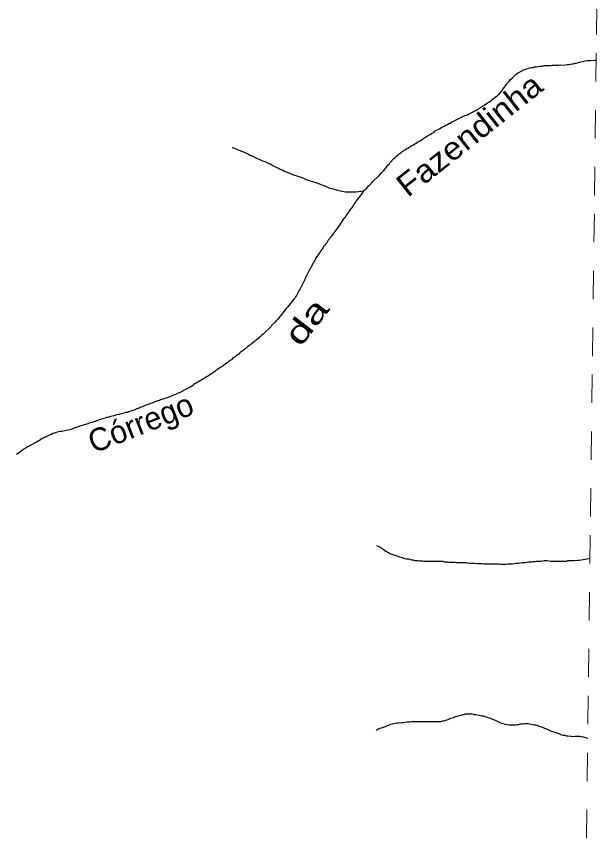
# Model space of a CAD drawing. Extents: x 652.3 to 678, y 7316.9 to 7344.9.
# Drawn here: x 675.832 to 677.88, y 7329.942 to 7332.83 of the extents above; entities that cross this region are included whole.
import ezdxf
from ezdxf.enums import TextEntityAlignment as Align

# ---------------------------------------------------------------- set-up
doc = ezdxf.new("R2010")
doc.units = 0
doc.header["$LTSCALE"] = 0.032
doc.linetypes.add('SHORT_DASHED', pattern=[2.7, 1.5, -1.2])
doc.layers.add('53', color=7, linetype='SHORT_DASHED', lineweight=13)
doc.layers.add('7', color=7, linetype='Continuous', lineweight=25)
doc.layers.add('61', color=7, linetype='Continuous')

msp = doc.modelspace()

# ---------------------------------------------------------------- linework, layer by layer
at = {"layer": '53'}
msp.add_lwpolyline([(677.795, 7326.5503), (677.802, 7327.1153), (677.8091, 7327.6804), (677.8162, 7328.2454), (677.8232, 7328.8105), (677.8303, 7329.3756), (677.8374, 7329.9406), (677.8444, 7330.5057), (677.8515, 7331.0708), (677.8585, 7331.6358), (677.8656, 7332.2009), (677.8726, 7332.766), (677.8797, 7333.331)], dxfattribs=at)
at = {"layer": '7'}
for points in [[(677.2561, 7332.3955), (677.2609, 7332.3979), (677.2648, 7332.4011), (677.2688, 7332.4043), (677.2736, 7332.4067), (677.2776, 7332.4098), (677.2823, 7332.4122), (677.2871, 7332.4154), (677.2919, 7332.4186), (677.2967, 7332.421), (677.3014, 7332.4234), (677.3054, 7332.4274), (677.3102, 7332.4297), (677.315, 7332.4329), (677.3197, 7332.4353), (677.3245, 7332.4385), (677.3388, 7332.4457), (677.3436, 7332.4488), (677.3484, 7332.4504), (677.3532, 7332.4536), (677.3579, 7332.4552), (677.3619, 7332.4584), (677.3667, 7332.46), (677.3858, 7332.4695), (677.3905, 7332.4719), (677.4096, 7332.4815), (677.4192, 7332.4846), (677.424, 7332.487), (677.4287, 7332.4902), (677.4335, 7332.4918), (677.4383, 7332.495), (677.4431, 7332.4974), (677.4478, 7332.4998), (677.4526, 7332.5029), (677.4622, 7332.5077), (677.4661, 7332.5109), (677.4709, 7332.5141), (677.4757, 7332.5165), (677.4797, 7332.5197), (677.4844, 7332.5228), (677.4892, 7332.526), (677.494, 7332.5284), (677.498, 7332.5316), (677.5019, 7332.5348), (677.5059, 7332.538), (677.5099, 7332.5411), (677.5139, 7332.5443), (677.5179, 7332.5475), (677.5226, 7332.5507), (677.5266, 7332.5539), (677.5306, 7332.5571), (677.5338, 7332.5618), (677.5401, 7332.5698), (677.5433, 7332.5746), (677.5497, 7332.5825), (677.5561, 7332.5921), (677.564, 7332.6), (677.5704, 7332.608), (677.5744, 7332.612), (677.5783, 7332.6159), (677.5863, 7332.6239), (677.5903, 7332.6271), (677.595, 7332.6303), (677.599, 7332.6334), (677.6181, 7332.643), (677.6277, 7332.6462), (677.6332, 7332.6478), (677.638, 7332.6494), (677.6436, 7332.6501), (677.6491, 7332.6509), (677.6547, 7332.6525), (677.6619, 7332.6533), (677.6674, 7332.6541), (677.673, 7332.6549), (677.6786, 7332.6557), (677.6842, 7332.6557), (677.6889, 7332.6573), (677.7056, 7332.6573), (677.7112, 7332.6581), (677.7168, 7332.6589), (677.7391, 7332.6589), (677.747, 7332.6597), (677.7582, 7332.6589), (677.7693, 7332.6605), (677.7749, 7332.6605), (677.7804, 7332.6621), (677.786, 7332.6629), (677.7916, 7332.6637), (677.7964, 7332.6653), (677.8019, 7332.6661), (677.8075, 7332.6677), (677.8123, 7332.6692), (677.8178, 7332.67), (677.8226, 7332.6716), (677.8274, 7332.6732), (677.833, 7332.674), (677.8385, 7332.6756), (677.8497, 7332.6756), (677.8672, 7332.6764), (677.8715, 7332.6766)], [(676.5905, 7332.3694), (676.5909, 7332.3693), (676.5957, 7332.3677), (676.6004, 7332.3661), (676.6052, 7332.3645), (676.6148, 7332.3597), (676.6195, 7332.3581), (676.6243, 7332.3557), (676.6338, 7332.3526), (676.6482, 7332.3454), (676.6529, 7332.3422), (676.6577, 7332.3406), (676.6625, 7332.3382), (676.6673, 7332.3359), (676.672, 7332.3335), (676.6768, 7332.3319), (676.6816, 7332.3295), (676.6864, 7332.3279), (676.6911, 7332.3255), (676.6959, 7332.3239), (676.7007, 7332.3215), (676.7055, 7332.3199), (676.7198, 7332.3128), (676.7246, 7332.3112), (676.7341, 7332.3064), (676.7389, 7332.304), (676.7628, 7332.2921), (676.7675, 7332.2905), (676.7723, 7332.2873), (676.7771, 7332.2849), (676.7818, 7332.2833), (676.7866, 7332.2809), (676.7962, 7332.2778), (676.8009, 7332.2754), (676.8105, 7332.2722), (676.8153, 7332.2706), (676.8248, 7332.2674), (676.8304, 7332.2658), (676.8352, 7332.2642), (676.8399, 7332.2619), (676.8447, 7332.2603), (676.8543, 7332.2555), (676.8686, 7332.2507), (676.8741, 7332.2491), (676.8885, 7332.2443), (676.8932, 7332.2428), (676.898, 7332.2412), (676.9028, 7332.2388), (676.9171, 7332.234), (676.9219, 7332.2316), (676.9267, 7332.23), (676.9314, 7332.2276), (676.9362, 7332.226), (676.941, 7332.2245), (676.9466, 7332.2237), (676.9609, 7332.2189), (676.9664, 7332.2181), (676.9712, 7332.2165), (676.9776, 7332.2157), (676.984, 7332.2149), (676.9887, 7332.2133), (677.0166, 7332.2133), (677.0261, 7332.2133), (677.0532, 7332.2165)], [(677.0532, 7332.2165), (677.0643, 7332.226), (677.0675, 7332.23), (677.0707, 7332.234), (677.0747, 7332.238), (677.0786, 7332.2412), (677.0818, 7332.2451), (677.0858, 7332.2491), (677.0898, 7332.2531), (677.1017, 7332.265), (677.1057, 7332.2682), (677.1089, 7332.2722), (677.1168, 7332.2802), (677.12, 7332.2841), (677.124, 7332.2881), (677.1335, 7332.3), (677.1367, 7332.304), (677.1399, 7332.308), (677.1439, 7332.312), (677.1471, 7332.3168), (677.159, 7332.3287), (677.163, 7332.3319), (677.1662, 7332.3359), (677.1701, 7332.3398), (677.1749, 7332.343), (677.1789, 7332.347), (677.1837, 7332.3502), (677.1876, 7332.3534), (677.1924, 7332.3565), (677.1964, 7332.3597), (677.2012, 7332.3621), (677.2059, 7332.3653), (677.2107, 7332.3685), (677.2155, 7332.3709), (677.2195, 7332.374), (677.2243, 7332.3764), (677.229, 7332.3788), (677.2338, 7332.382), (677.2386, 7332.3844), (677.2426, 7332.3876), (677.2521, 7332.3923), (677.2561, 7332.3955)], [(677.0532, 7332.2165), (677.0452, 7332.2038), (677.042, 7332.1998), (677.0357, 7332.1926), (677.0277, 7332.1815), (677.0245, 7332.1767), (677.0214, 7332.1727), (677.0182, 7332.168), (677.0158, 7332.1632), (677.0126, 7332.1592), (677.0094, 7332.1544), (677.0062, 7332.1505), (677.003, 7332.1457), (676.9999, 7332.1417), (676.9967, 7332.1369), (676.9935, 7332.1322), (676.9903, 7332.1282), (676.9871, 7332.1234), (676.984, 7332.1194), (676.9808, 7332.1146), (676.9776, 7332.1107), (676.968, 7332.0963), (676.9649, 7332.0916), (676.9617, 7332.0868), (676.9553, 7332.0788), (676.9489, 7332.0693), (676.9426, 7332.0613), (676.9394, 7332.0566), (676.9354, 7332.0526), (676.933, 7332.0478), (676.9291, 7332.0438), (676.9267, 7332.0391), (676.9235, 7332.0343)], [(676.9235, 7332.0343), (676.9203, 7332.0303), (676.9171, 7332.0255), (676.9139, 7332.0216), (676.9076, 7332.012), (676.9012, 7332.004), (676.8988, 7331.9993), (676.8956, 7331.9953), (676.8924, 7331.9905), (676.8893, 7331.9857), (676.8829, 7331.9762), (676.8813, 7331.9714), (676.8781, 7331.9674), (676.8757, 7331.9627), (676.8726, 7331.9579), (676.871, 7331.9531), (676.8678, 7331.9483), (676.8654, 7331.9436), (676.863, 7331.9388), (676.8558, 7331.9245), (676.8535, 7331.9197), (676.8503, 7331.9149), (676.8487, 7331.9102), (676.8463, 7331.9054), (676.8447, 7331.9006), (676.8375, 7331.8863), (676.8352, 7331.8815), (676.8304, 7331.872), (676.8272, 7331.8672), (676.8248, 7331.8624), (676.82, 7331.8529), (676.8169, 7331.8489), (676.8137, 7331.8441), (676.8113, 7331.8393), (676.8081, 7331.8354), (676.7858, 7331.8075), (676.7826, 7331.8035), (676.7604, 7331.7757), (676.7564, 7331.7717), (676.75, 7331.7638), (676.746, 7331.7598), (676.7429, 7331.7558), (676.7309, 7331.7439), (676.7277, 7331.7399), (676.7039, 7331.716), (676.6999, 7331.7128), (676.6959, 7331.7096), (676.6919, 7331.7057), (676.688, 7331.7025), (676.684, 7331.6985), (676.68, 7331.6953), (676.676, 7331.6921), (676.672, 7331.689), (676.6681, 7331.6858), (676.6641, 7331.6826), (676.6593, 7331.6794), (676.6553, 7331.6754), (676.6506, 7331.6722), (676.6466, 7331.6691), (676.6426, 7331.6659), (676.6386, 7331.6627), (676.6346, 7331.6595), (676.6307, 7331.6563), (676.6267, 7331.6531), (676.6219, 7331.65), (676.6179, 7331.6468), (676.614, 7331.6428), (676.61, 7331.6396), (676.6052, 7331.6364), (676.6012, 7331.6333), (676.5972, 7331.6301), (676.5925, 7331.6269), (676.5885, 7331.6229), (676.5837, 7331.6197), (676.5797, 7331.6165), (676.5758, 7331.6134), (676.571, 7331.6102), (676.5662, 7331.607), (676.5622, 7331.6038), (676.5583, 7331.6006), (676.5535, 7331.5982), (676.5495, 7331.5951), (676.5447, 7331.5919), (676.54, 7331.5887), (676.5352, 7331.5855), (676.5312, 7331.5823), (676.5264, 7331.5792), (676.5217, 7331.576), (676.5169, 7331.5728), (676.5121, 7331.5696), (676.5073, 7331.5664), (676.5026, 7331.5632), (676.4978, 7331.5608), (676.4938, 7331.5577), (676.489, 7331.5553), (676.4843, 7331.5521), (676.4795, 7331.5497), (676.4755, 7331.5465), (676.466, 7331.5418), (676.4612, 7331.5386), (676.4564, 7331.5354)], [(676.4564, 7331.5354), (676.4524, 7331.5322), (676.4485, 7331.529), (676.4294, 7331.5195), (676.4246, 7331.5163), (676.4055, 7331.5067), (676.4007, 7331.5052), (676.3912, 7331.5004), (676.3816, 7331.4972), (676.3721, 7331.4924), (676.3625, 7331.4892), (676.3577, 7331.4876), (676.3434, 7331.4829), (676.3386, 7331.4813), (676.3339, 7331.4797), (676.3283, 7331.4781), (676.3235, 7331.4757), (676.3188, 7331.4741), (676.314, 7331.4725), (676.3092, 7331.4701), (676.3044, 7331.4685), (676.2997, 7331.4662), (676.2853, 7331.4614), (676.2806, 7331.459), (676.2758, 7331.4574), (676.2702, 7331.4558), (676.2654, 7331.4534), (676.2607, 7331.451), (676.2559, 7331.4495), (676.2511, 7331.4479), (676.2463, 7331.4455), (676.2408, 7331.4447), (676.236, 7331.4423), (676.2312, 7331.4407), (676.2217, 7331.4375), (676.2161, 7331.4367), (676.2105, 7331.4351), (676.201, 7331.4319), (676.1954, 7331.4304), (676.1899, 7331.4296), (676.1843, 7331.4288), (676.1747, 7331.4256), (676.1692, 7331.4248), (676.1644, 7331.4232), (676.1596, 7331.4216), (676.1548, 7331.42), (676.1493, 7331.4192), (676.1445, 7331.4176), (676.1397, 7331.416), (676.1342, 7331.4144), (676.1294, 7331.4129), (676.1238, 7331.4113), (676.119, 7331.4089), (676.1047, 7331.4041), (676.0991, 7331.4025), (676.088, 7331.3993), (676.0832, 7331.3977), (676.0785, 7331.3961), (676.0641, 7331.3914), (676.0586, 7331.3898), (676.049, 7331.3866), (676.0442, 7331.385), (676.0395, 7331.3834), (676.0339, 7331.3818), (676.0291, 7331.3802), (676.0244, 7331.3778), (676.0196, 7331.3762), (676.014, 7331.3755), (676.0076, 7331.3739), (676.0029, 7331.3723), (675.9917, 7331.3707), (675.9862, 7331.3699), (675.9806, 7331.3691), (675.9758, 7331.3675), (675.9702, 7331.3659), (675.9655, 7331.3643), (675.9607, 7331.3627), (675.9559, 7331.3603), (675.9511, 7331.3587), (675.9368, 7331.3516), (675.9321, 7331.35), (675.9273, 7331.3468), (675.9225, 7331.3452), (675.9177, 7331.342), (675.913, 7331.3389), (675.9082, 7331.3365), (675.9034, 7331.3333), (675.8986, 7331.3309), (675.8947, 7331.3277), (675.8899, 7331.3261), (675.8851, 7331.3229), (675.8803, 7331.3206), (675.8756, 7331.3174), (675.8708, 7331.3158), (675.866, 7331.3134), (675.862, 7331.3102), (675.8573, 7331.3078), (675.8533, 7331.3046), (675.8405, 7331.2951), (675.8329, 7331.2894), (675.8323, 7331.2889)], [(677.0986, 7330.969), (677.099, 7330.9688), (677.1049, 7330.9665), (677.1089, 7330.9649), (677.1136, 7330.9625), (677.1176, 7330.9593), (677.1224, 7330.9561), (677.1264, 7330.9529), (677.1312, 7330.9498), (677.1359, 7330.9474), (677.1407, 7330.9442), (677.1455, 7330.9418), (677.1598, 7330.937), (677.1646, 7330.9354), (677.1741, 7330.9323), (677.1789, 7330.9299), (677.1845, 7330.9283), (677.1892, 7330.9267), (677.194, 7330.9251), (677.1988, 7330.9235), (677.2044, 7330.9227), (677.2107, 7330.9219), (677.2163, 7330.9211), (677.2219, 7330.9195), (677.2274, 7330.9187), (677.2322, 7330.9171), (677.2378, 7330.9171), (677.2433, 7330.9163), (677.2489, 7330.9155), (677.2601, 7330.9155), (677.2656, 7330.9148), (677.2712, 7330.914), (677.3325, 7330.914), (677.3372, 7330.9124), (677.3484, 7330.9124), (677.3532, 7330.9108), (677.3754, 7330.9108), (677.3802, 7330.9092), (677.4136, 7330.9092), (677.4192, 7330.9084), (677.4248, 7330.9076), (677.4415, 7330.9076), (677.4526, 7330.906), (677.4693, 7330.906), (677.4773, 7330.9052), (677.4852, 7330.9044), (677.4964, 7330.9044), (677.5019, 7330.9052), (677.5139, 7330.9052), (677.5195, 7330.9044), (677.5306, 7330.9044), (677.5362, 7330.9036), (677.5529, 7330.9036), (677.5592, 7330.9044), (677.5648, 7330.9044), (677.5704, 7330.9052), (677.5767, 7330.9052), (677.5823, 7330.906), (677.5879, 7330.9068), (677.5942, 7330.9076), (677.5998, 7330.9076), (677.6054, 7330.9084), (677.611, 7330.9092), (677.6165, 7330.9092), (677.6221, 7330.91), (677.6332, 7330.9116), (677.6388, 7330.9116), (677.6444, 7330.9124), (677.6499, 7330.9132), (677.6555, 7330.9132), (677.6603, 7330.9148), (677.677, 7330.9148), (677.6826, 7330.9155), (677.6881, 7330.9163), (677.6993, 7330.9163), (677.7048, 7330.9155), (677.7104, 7330.9148), (677.7438, 7330.9148), (677.7494, 7330.914), (677.755, 7330.9148), (677.7669, 7330.9148), (677.7717, 7330.9163), (677.7948, 7330.9163), (677.8059, 7330.9179), (677.8115, 7330.9179), (677.8401, 7330.9227), (677.8497, 7330.9243)], [(677.1304, 7330.3331), (677.1351, 7330.3355), (677.1399, 7330.3371), (677.1447, 7330.3387), (677.1495, 7330.3411), (677.1542, 7330.3427), (677.1598, 7330.3434), (677.1654, 7330.3442), (677.1701, 7330.3458), (677.1757, 7330.3458), (677.1869, 7330.3474), (677.1924, 7330.3474), (677.198, 7330.3482), (677.2052, 7330.349), (677.2163, 7330.349), (677.2219, 7330.3498), (677.2274, 7330.3506), (677.2831, 7330.3506), (677.2903, 7330.3506), (677.2982, 7330.3498), (677.3205, 7330.3498), (677.3261, 7330.3506), (677.3309, 7330.3522), (677.3364, 7330.353), (677.346, 7330.3562), (677.3508, 7330.3578), (677.3555, 7330.3594), (677.3603, 7330.3617), (677.3699, 7330.3649), (677.3746, 7330.3665), (677.3858, 7330.3697), (677.3905, 7330.3713), (677.3961, 7330.3729), (677.4009, 7330.3745), (677.4065, 7330.3753), (677.412, 7330.3769), (677.4351, 7330.3769), (677.4415, 7330.3753), (677.4478, 7330.3753), (677.4542, 7330.3737), (677.4598, 7330.3729), (677.4645, 7330.3713), (677.4693, 7330.3697), (677.4749, 7330.3697), (677.4797, 7330.3681), (677.4852, 7330.3665), (677.49, 7330.3649), (677.4996, 7330.3617), (677.5043, 7330.3594), (677.5091, 7330.3578), (677.5139, 7330.3562), (677.5187, 7330.3538), (677.5282, 7330.349), (677.533, 7330.3474), (677.5378, 7330.345), (677.5425, 7330.3434), (677.5473, 7330.3419), (677.5529, 7330.3411), (677.5584, 7330.3403), (677.5648, 7330.3387), (677.5871, 7330.3387), (677.5935, 7330.3403), (677.599, 7330.3403), (677.6038, 7330.3419), (677.6094, 7330.3419), (677.6149, 7330.3427), (677.6205, 7330.3434), (677.6316, 7330.3434), (677.6372, 7330.3427), (677.642, 7330.3411), (677.6476, 7330.3403), (677.6531, 7330.3387), (677.6587, 7330.3387), (677.6635, 7330.3371), (677.6682, 7330.3355), (677.673, 7330.3331), (677.6826, 7330.3299), (677.6873, 7330.3275), (677.6921, 7330.3259), (677.6969, 7330.3243), (677.7017, 7330.322), (677.7064, 7330.3196), (677.7112, 7330.318), (677.7255, 7330.3132), (677.7303, 7330.3116), (677.7351, 7330.3092), (677.7399, 7330.3076), (677.7446, 7330.306), (677.7494, 7330.3037), (677.755, 7330.3021), (677.7605, 7330.3021), (677.7661, 7330.3005), (677.7717, 7330.3005), (677.7828, 7330.2989), (677.7884, 7330.2981), (677.7979, 7330.2989), (677.8147, 7330.2989), (677.8202, 7330.2973), (677.8258, 7330.2965), (677.8418, 7330.292)], [(677.0971, 7330.3204), (677.1049, 7330.3243), (677.1065, 7330.3251), (677.1113, 7330.3267), (677.116, 7330.3283), (677.1304, 7330.3331)]]:
    msp.add_lwpolyline(points, dxfattribs=at)

# ---------------------------------------------------------------- texts
at = {"layer": '61'}
for s, rotation, width, p in [('Fazendinha', 38.383, 1.1, (677.4498, 7332.3822)), ('da', 52.154, 1.45, (676.8839, 7331.7322))]:
    msp.add_text(s, height=0.08, rotation=rotation, dxfattribs=dict(at, width=width)).set_placement(p, align=Align.CENTER)
msp.add_text('Córrego', height=0.08, rotation=21.549, dxfattribs=at).set_placement((676.2838, 7331.3632), align=Align.CENTER)

doc.saveas('drawing.dxf')
